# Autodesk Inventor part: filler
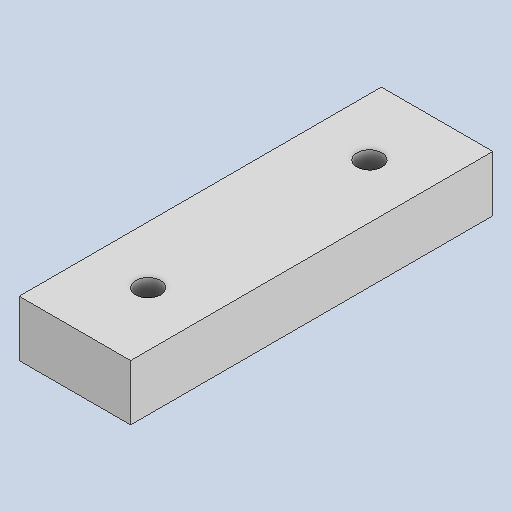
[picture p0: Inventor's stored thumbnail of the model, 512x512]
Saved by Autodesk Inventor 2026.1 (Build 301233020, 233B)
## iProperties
Created: 2026-11
Part Number: filler
Material: Generic
Document SubType Name: Modeling
Designer: hp
Density: 1 g/cm^3
Appearance: Default
Author: hp
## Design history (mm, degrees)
sketch "Sketch1"
  geometry: L1 (0, 0)-(20, 0); L2 (20, 0)-(20, -65); L3 (20, -65)-(0, -65); L4 (0, -65)-(0, 0)
  constraints: 8 end point, 2 parallel, 1 horizontal, 1 perpendicular
  dimensions: "d0" = 20 distance of L2.end L3.end; "d1" = 65 distance of L1.end L2.end
extrude "Extrusion1" new body sketch "Sketch1" distance "d2" = 10; taper "d3" = 0 deg
sketch "Sketch2"
  geometry: 1 further point
hole "Hole1" sketch "Sketch2" at (-9.75, -52.6) diameter "d4" = 4.5; stored, may be unused: countersink angle "d8" = 90 deg, drill point angle "d10" = 0 deg; dims "d5" = 6, "d6" = 4, "d7" = 2, "d9" = 8
sketch "Sketch3"
  geometry: 1 further point
hole "Hole2" sketch "Sketch3" at (-9.75, -12.9) diameter "d11" = 4.5; stored, may be unused: countersink angle "d15" = 90 deg, drill point angle "d17" = 0 deg; dims "d12" = 6, "d13" = 4, "d14" = 2, "d16" = 8
body "Solid1"
